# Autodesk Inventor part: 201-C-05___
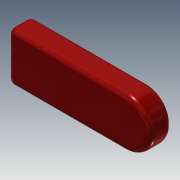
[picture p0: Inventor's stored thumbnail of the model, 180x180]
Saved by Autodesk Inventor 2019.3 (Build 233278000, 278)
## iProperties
Created: 2010-06
Part Number: 201-C-05___
Material: Ogólny
Document SubType Name: Modeling
Designer: CADENGINEERING4
Density: 1 g/cm^3
Appearance: Czerwona
Author: CADENGINEERING4
Revision Number: ANY
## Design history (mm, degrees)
feature "NONE"
node "Bryła1"
